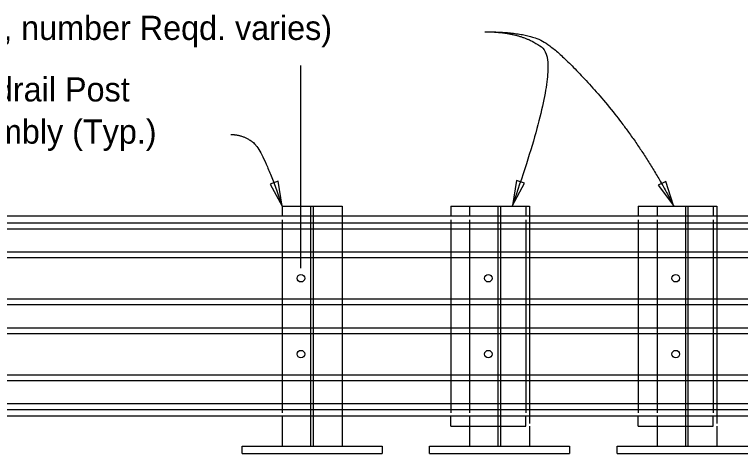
# Model space of a CAD drawing. Extents: x 21587 to 21656.3, y 56117.4 to 56157.3.
# Drawn here: x 21593.21 to 21599.26, y 56134.8 to 56138.46 of the extents above; entities that cross this region are included whole.
import ezdxf

# ---------------------------------------------------------------- set-up
doc = ezdxf.new("R2010")
doc.units = 0
for name, color, linetype in [('Border', 7, 'Continuous'), ('Patterning', 7, 'Continuous'), ('PlotBorder_dp', 7, 'Continuous'), ('TextMisc', 7, 'Continuous')]:
    doc.layers.add(name, color=color, linetype=linetype)

msp = doc.modelspace()

# ---------------------------------------------------------------- linework, layer by layer
at = {"layer": 'Border'}
for p, q in [((21595.4377, 56136.8635), (21595.9377, 56136.8635)), ((21595.4377, 56136.8635), (21595.4377, 56136.7802)), ((21595.9377, 56136.8635), (21595.9377, 56136.7802)), ((21599.7592, 56136.7801), (21587.6633, 56136.7801)), ((21587.6633, 56136.7246), (21599.7592, 56136.7246)), ((21587.6633, 56136.6764), (21599.7592, 56136.6764)), ((21587.6633, 56136.4835), (21599.7592, 56136.4835)), ((21587.6633, 56136.4353), (21599.7592, 56136.4353)), ((21587.6633, 56136.0914), (21599.7592, 56136.0914)), ((21587.6633, 56136.0431), (21599.7592, 56136.0431)), ((21587.6633, 56135.8503), (21599.7592, 56135.8503)), ((21587.6633, 56135.8022), (21599.7592, 56135.8022)), ((21587.6633, 56135.4582), (21599.7592, 56135.4582)), ((21587.6633, 56135.41), (21599.7592, 56135.41)), ((21587.6633, 56135.2172), (21599.7592, 56135.2172)), ((21587.6633, 56135.169), (21599.7592, 56135.169)), ((21599.7592, 56135.1134), (21587.6633, 56135.1134)), ((21595.4377, 56135.1135), (21595.4377, 56134.8635)), ((21595.9377, 56135.1134), (21595.9377, 56134.8635)), ((21595.1043, 56134.8635), (21596.271, 56134.8635)), ((21595.1043, 56134.801), (21595.1043, 56134.8635)), ((21595.4377, 56134.8635), (21595.9377, 56134.8635)), ((21596.271, 56134.8635), (21596.271, 56134.801)), ((21595.1043, 56134.801), (21596.271, 56134.801))]:
    msp.add_line(p, q, dxfattribs=at)
for centre in [(21595.5939, 56136.2634), (21595.5939, 56135.6303)]:
    msp.add_circle(centre, 0.0312, dxfattribs=at)
at = {"layer": 'Patterning'}
for p, q in [((21595.6772, 56134.8635), (21595.6772, 56136.8635)), ((21595.6981, 56134.8635), (21595.6981, 56136.8635)), ((21597.0002, 56136.8635), (21597.5002, 56136.8635)), ((21597.0002, 56136.8635), (21597.0002, 56136.7802)), ((21597.2397, 56134.8635), (21597.2397, 56136.8635)), ((21597.2606, 56134.8635), (21597.2606, 56136.8635)), ((21597.5002, 56136.8635), (21597.5002, 56135.0505)), ((21598.5627, 56136.8635), (21599.0627, 56136.8635)), ((21598.5627, 56136.8635), (21598.5627, 56136.7802)), ((21598.8022, 56134.8635), (21598.8022, 56136.8635)), ((21598.8231, 56134.8635), (21598.8231, 56136.8635)), ((21599.0627, 56136.8635), (21599.0627, 56135.0505)), ((21595.9377, 56136.7801), (21595.9377, 56135.1134)), ((21595.4377, 56136.7516), (21595.4377, 56135.1398)), ((21597.0002, 56136.7516), (21597.0002, 56135.1398)), ((21598.5627, 56136.7516), (21598.5627, 56135.1398)), ((21597.0002, 56135.1135), (21597.0002, 56134.8635)), ((21598.5627, 56135.1135), (21598.5627, 56134.8635)), ((21597.5002, 56135.0302), (21597.5002, 56134.8635)), ((21599.0627, 56135.0302), (21599.0627, 56134.8635)), ((21596.6668, 56134.8635), (21597.8335, 56134.8635)), ((21596.6668, 56134.801), (21596.6668, 56134.8635)), ((21597.0002, 56134.8635), (21597.5002, 56134.8635)), ((21597.8335, 56134.8635), (21597.8335, 56134.801)), ((21598.2293, 56134.8635), (21599.396, 56134.8635)), ((21598.2293, 56134.801), (21598.2293, 56134.8635)), ((21598.5627, 56134.8635), (21599.0627, 56134.8635)), ((21596.6668, 56134.801), (21597.8335, 56134.801)), ((21598.2293, 56134.801), (21599.396, 56134.801))]:
    msp.add_line(p, q, dxfattribs=at)
for centre in [(21597.1564, 56136.2634), (21598.7189, 56136.2634), (21597.1564, 56135.6303), (21598.7189, 56135.6303)]:
    msp.add_circle(centre, 0.0312, dxfattribs=at)
at = {"layer": 'PlotBorder_dp'}
msp.add_line((21595.5939, 56136.3484), (21595.5939, 56138.0393), dxfattribs=at)
for points in [[(21595.4377, 56136.8635), (21595.4035, 56137.072), (21595.3368, 56137.0491)], [(21597.3567, 56136.8707), (21597.4591, 56137.0555), (21597.3925, 56137.0789)], [(21598.7008, 56136.8707), (21598.6361, 56137.0718), (21598.5735, 56137.0392)]]:
    msp.add_lwpolyline(points, close=True, dxfattribs=at)
for points in [[(21597.126, 56138.3201), (21597.437, 56138.3201), (21597.773, 56138.0543), (21597.3567, 56136.8707)], [(21597.126, 56138.3201), (21597.437, 56138.3201), (21597.7379, 56138.1847), (21598.435, 56137.3823), (21598.7008, 56136.8707)], [(21595.0096, 56137.4625), (21595.1087, 56137.4625), (21595.2754, 56137.3371), (21595.4377, 56136.8635)]]:
    msp.add_open_spline(points, degree=2, dxfattribs=at)
at = {"layer": 'TextMisc'}
for p, q in [((21596.8439, 56136.8635), (21597.4689, 56136.8635)), ((21596.8439, 56136.8635), (21596.8439, 56136.7802)), ((21597.4689, 56136.8635), (21597.4689, 56136.7802)), ((21598.4064, 56136.8635), (21599.0314, 56136.8635)), ((21598.4064, 56136.8635), (21598.4064, 56136.7802)), ((21599.0314, 56136.8635), (21599.0314, 56136.7802)), ((21596.8439, 56136.7516), (21596.8439, 56135.1398)), ((21597.4689, 56136.7516), (21597.4689, 56135.1398)), ((21598.4064, 56136.7516), (21598.4064, 56135.1398)), ((21599.0314, 56136.7516), (21599.0314, 56135.1398)), ((21596.8439, 56135.0302), (21596.8439, 56135.1135)), ((21597.4689, 56135.0302), (21597.4689, 56135.1135)), ((21598.4064, 56135.0302), (21598.4064, 56135.1135)), ((21599.0314, 56135.0302), (21599.0314, 56135.1135)), ((21596.8439, 56135.0302), (21597.4689, 56135.0302)), ((21598.4064, 56135.0302), (21599.0314, 56135.0302))]:
    msp.add_line(p, q, dxfattribs=at)

# ---------------------------------------------------------------- texts
at = {"layer": 'PlotBorder_dp'}
for s, p in [('(shown dashed, number Reqd. varies)', (21591.2828, 56138.2516)), ('Guardrail Post ', (21592.443, 56137.7383)), ('Assembly (Typ.)', (21592.443, 56137.3863))]:
    msp.add_text(s, height=0.2016, dxfattribs=at).set_placement(p)

doc.saveas('drawing.dxf')
